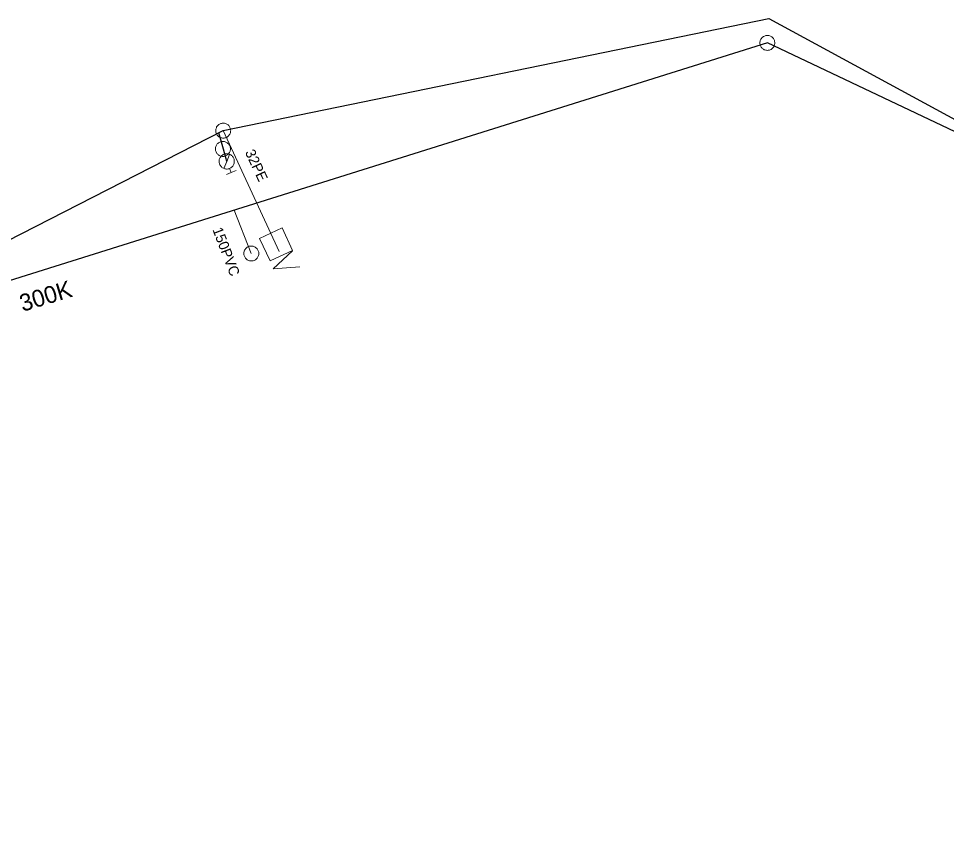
# Model space of a CAD drawing. Extents: x -741806 to -738704, y -1059275 to -1055387.
# Drawn here: x -740464.1 to -740409.8, y -1057633.9 to -1057586.1 of the extents above; entities that cross this region are included whole.
import ezdxf

# ---------------------------------------------------------------- set-up
doc = ezdxf.new("R2010")
doc.units = 0
doc.header["$LTSCALE"] = 0.4
for name, color, linetype, lineweight in [('2', 7, 'Continuous', 25), ('21', 7, 'Continuous', 13), ('3', 7, 'Continuous', 13), ('46', 7, 'Continuous', 13), ('50', 7, 'Continuous', 13), ('51', 7, 'Continuous', 13), ('52', 7, 'Continuous', 25), ('56', 7, 'Continuous', 13), ('60', 7, 'Continuous', 13)]:
    doc.layers.add(name, color=color, linetype=linetype, lineweight=lineweight)
for name, color, linetype in [('5', 7, 'Continuous'), ('54', 7, 'Continuous'), ('55', 7, 'Continuous')]:
    doc.layers.add(name, color=color, linetype=linetype)

msp = doc.modelspace()

# ---------------------------------------------------------------- linework, layer by layer
at = {"layer": '2'}
for p, q in [((-740420.289, -1057587.53), (-740504.877, -1057614.071)), ((-740388.249, -1057602.723), (-740420.289, -1057587.53))]:
    msp.add_line(p, q, dxfattribs=at)
at = {"layer": '21'}
msp.add_line((-740452.151, -1057592.668), (-740448.87, -1057599.747), dxfattribs=at)
at = {"layer": '3'}
msp.add_lwpolyline([(-740420.707, -1057587.66), (-740420.69, -1057587.702), (-740420.67, -1057587.743), (-740420.645, -1057587.782), (-740420.617, -1057587.818), (-740420.585, -1057587.85), (-740420.549, -1057587.88), (-740420.511, -1057587.905), (-740420.471, -1057587.927), (-740420.428, -1057587.943), (-740420.384, -1057587.955), (-740420.339, -1057587.963), (-740420.293, -1057587.966), (-740420.248, -1057587.964), (-740420.202, -1057587.958), (-740420.158, -1057587.946), (-740420.115, -1057587.93), (-740420.074, -1057587.909), (-740420.035, -1057587.886), (-740419.999, -1057587.856), (-740419.967, -1057587.824), (-740419.938, -1057587.789), (-740419.913, -1057587.752), (-740419.891, -1057587.71), (-740419.874, -1057587.668), (-740419.862, -1057587.624), (-740419.855, -1057587.578), (-740419.851, -1057587.533), (-740419.853, -1057587.487), (-740419.86, -1057587.442), (-740419.872, -1057587.397), (-740419.887, -1057587.355), (-740419.908, -1057587.314), (-740419.932, -1057587.275), (-740419.962, -1057587.239), (-740419.993, -1057587.207), (-740420.028, -1057587.177), (-740420.066, -1057587.152), (-740420.108, -1057587.131), (-740420.149, -1057587.114), (-740420.193, -1057587.102), (-740420.239, -1057587.094), (-740420.285, -1057587.091), (-740420.33, -1057587.092), (-740420.375, -1057587.099), (-740420.42, -1057587.111), (-740420.463, -1057587.127), (-740420.504, -1057587.147), (-740420.542, -1057587.172), (-740420.578, -1057587.201), (-740420.611, -1057587.233), (-740420.64, -1057587.268), (-740420.666, -1057587.306), (-740420.686, -1057587.347), (-740420.704, -1057587.389), (-740420.716, -1057587.434), (-740420.724, -1057587.479), (-740420.726, -1057587.524), (-740420.724, -1057587.57), (-740420.717, -1057587.615), (-740420.707, -1057587.659)], dxfattribs=at)
at = {"layer": '46'}
msp.add_lwpolyline([(-740450.665, -1057599.461), (-740450.706, -1057599.48), (-740450.746, -1057599.503), (-740450.783, -1057599.53), (-740450.816, -1057599.561), (-740450.847, -1057599.595), (-740450.874, -1057599.633), (-740450.896, -1057599.672), (-740450.915, -1057599.714), (-740450.928, -1057599.758), (-740450.938, -1057599.802), (-740450.942, -1057599.848), (-740450.943, -1057599.894), (-740450.937, -1057599.939), (-740450.928, -1057599.984), (-740450.913, -1057600.028), (-740450.894, -1057600.07), (-740450.871, -1057600.109), (-740450.844, -1057600.146), (-740450.813, -1057600.18), (-740450.778, -1057600.21), (-740450.741, -1057600.237), (-740450.702, -1057600.259), (-740450.66, -1057600.278), (-740450.616, -1057600.292), (-740450.571, -1057600.301), (-740450.526, -1057600.305), (-740450.48, -1057600.305), (-740450.434, -1057600.3), (-740450.39, -1057600.29), (-740450.346, -1057600.275), (-740450.305, -1057600.257), (-740450.265, -1057600.234), (-740450.228, -1057600.207), (-740450.194, -1057600.175), (-740450.164, -1057600.142), (-740450.137, -1057600.104), (-740450.115, -1057600.065), (-740450.096, -1057600.022), (-740450.083, -1057599.979), (-740450.073, -1057599.935), (-740450.069, -1057599.889), (-740450.068, -1057599.843), (-740450.073, -1057599.797), (-740450.083, -1057599.753), (-740450.098, -1057599.709), (-740450.117, -1057599.667), (-740450.14, -1057599.628), (-740450.167, -1057599.591), (-740450.198, -1057599.557), (-740450.233, -1057599.527), (-740450.27, -1057599.5), (-740450.309, -1057599.477), (-740450.351, -1057599.459), (-740450.395, -1057599.445), (-740450.44, -1057599.436), (-740450.486, -1057599.431), (-740450.531, -1057599.432), (-740450.577, -1057599.437), (-740450.621, -1057599.447), (-740450.664, -1057599.46)], dxfattribs=at)
at = {"layer": '50'}
for p, q in [((-740451.948, -1057594.472), (-740451.775, -1057594.059)), ((-740451.948, -1057594.472), (-740452.122, -1057594.88)), ((-740451.967, -1057595.234), (-740451.683, -1057595.118)), ((-740451.778, -1057594.886), (-740451.683, -1057595.118)), ((-740451.398, -1057595.002), (-740451.683, -1057595.118))]:
    msp.add_line(p, q, dxfattribs=at)
msp.add_lwpolyline([(-740452.361, -1057594.637), (-740452.339, -1057594.681), (-740452.317, -1057594.722), (-740452.288, -1057594.759), (-740452.256, -1057594.793), (-740452.223, -1057594.822), (-740452.183, -1057594.85), (-740452.143, -1057594.872), (-740452.099, -1057594.891), (-740452.055, -1057594.906), (-740452.009, -1057594.913), (-740451.963, -1057594.918), (-740451.916, -1057594.919), (-740451.869, -1057594.911), (-740451.824, -1057594.901), (-740451.78, -1057594.886), (-740451.739, -1057594.866), (-740451.699, -1057594.845), (-740451.661, -1057594.815), (-740451.627, -1057594.783), (-740451.595, -1057594.747), (-740451.569, -1057594.71), (-740451.546, -1057594.669), (-740451.528, -1057594.626), (-740451.514, -1057594.582), (-740451.504, -1057594.535), (-740451.5, -1057594.489), (-740451.501, -1057594.443), (-740451.506, -1057594.395), (-740451.518, -1057594.351), (-740451.53, -1057594.306), (-740451.551, -1057594.262), (-740451.576, -1057594.223), (-740451.602, -1057594.187), (-740451.635, -1057594.151), (-740451.67, -1057594.121), (-740451.708, -1057594.093), (-740451.749, -1057594.072), (-740451.792, -1057594.052), (-740451.838, -1057594.038), (-740451.882, -1057594.031), (-740451.931, -1057594.027), (-740451.976, -1057594.028), (-740452.022, -1057594.031), (-740452.07, -1057594.042), (-740452.114, -1057594.057), (-740452.155, -1057594.077), (-740452.195, -1057594.102), (-740452.233, -1057594.13), (-740452.267, -1057594.161), (-740452.298, -1057594.197), (-740452.324, -1057594.234), (-740452.348, -1057594.276), (-740452.366, -1057594.318), (-740452.38, -1057594.362), (-740452.387, -1057594.409), (-740452.394, -1057594.455), (-740452.393, -1057594.502), (-740452.385, -1057594.547), (-740452.375, -1057594.593)], close=True, dxfattribs=at)
at = {"layer": '51'}
for points in [[(-740451.967, -1057593.064), (-740451.927, -1057593.043), (-740451.889, -1057593.018), (-740451.854, -1057592.988), (-740451.822, -1057592.956), (-740451.794, -1057592.92), (-740451.769, -1057592.881), (-740451.749, -1057592.84), (-740451.733, -1057592.797), (-740451.723, -1057592.752), (-740451.716, -1057592.708), (-740451.714, -1057592.661), (-740451.717, -1057592.615), (-740451.724, -1057592.57), (-740451.737, -1057592.527), (-740451.754, -1057592.484), (-740451.776, -1057592.443), (-740451.801, -1057592.405), (-740451.83, -1057592.37), (-740451.864, -1057592.338), (-740451.9, -1057592.31), (-740451.939, -1057592.286), (-740451.979, -1057592.265), (-740452.023, -1057592.25), (-740452.067, -1057592.238), (-740452.112, -1057592.232), (-740452.159, -1057592.23), (-740452.203, -1057592.234), (-740452.249, -1057592.242), (-740452.293, -1057592.254), (-740452.336, -1057592.271), (-740452.376, -1057592.292), (-740452.413, -1057592.318), (-740452.449, -1057592.347), (-740452.481, -1057592.38), (-740452.509, -1057592.416), (-740452.534, -1057592.455), (-740452.553, -1057592.496), (-740452.57, -1057592.539), (-740452.58, -1057592.583), (-740452.587, -1057592.628), (-740452.589, -1057592.674), (-740452.586, -1057592.721), (-740452.578, -1057592.765), (-740452.566, -1057592.809), (-740452.548, -1057592.852), (-740452.527, -1057592.893), (-740452.501, -1057592.93), (-740452.473, -1057592.966), (-740452.439, -1057592.997), (-740452.403, -1057593.026), (-740452.364, -1057593.05), (-740452.324, -1057593.071), (-740452.28, -1057593.086), (-740452.236, -1057593.097), (-740452.19, -1057593.104), (-740452.144, -1057593.105), (-740452.099, -1057593.102), (-740452.054, -1057593.094), (-740452.01, -1057593.082), (-740451.968, -1057593.065)], [(-740452.262, -1057593.314), (-740452.306, -1057593.326), (-740452.348, -1057593.342), (-740452.389, -1057593.364), (-740452.427, -1057593.388), (-740452.463, -1057593.417), (-740452.495, -1057593.45), (-740452.523, -1057593.486), (-740452.549, -1057593.524), (-740452.569, -1057593.565), (-740452.585, -1057593.608), (-740452.597, -1057593.652), (-740452.604, -1057593.698), (-740452.607, -1057593.744), (-740452.604, -1057593.789), (-740452.596, -1057593.834), (-740452.584, -1057593.879), (-740452.568, -1057593.921), (-740452.547, -1057593.962), (-740452.521, -1057594), (-740452.492, -1057594.036), (-740452.459, -1057594.068), (-740452.424, -1057594.097), (-740452.385, -1057594.121), (-740452.345, -1057594.142), (-740452.301, -1057594.158), (-740452.257, -1057594.17), (-740452.212, -1057594.177), (-740452.166, -1057594.179), (-740452.12, -1057594.176), (-740452.075, -1057594.169), (-740452.032, -1057594.157), (-740451.989, -1057594.14), (-740451.948, -1057594.119), (-740451.91, -1057594.094), (-740451.874, -1057594.065), (-740451.842, -1057594.032), (-740451.814, -1057593.997), (-740451.788, -1057593.958), (-740451.768, -1057593.917), (-740451.752, -1057593.875), (-740451.74, -1057593.83), (-740451.733, -1057593.785), (-740451.731, -1057593.739), (-740451.733, -1057593.694), (-740451.741, -1057593.648), (-740451.753, -1057593.604), (-740451.77, -1057593.561), (-740451.79, -1057593.521), (-740451.816, -1057593.482), (-740451.845, -1057593.447), (-740451.878, -1057593.415), (-740451.913, -1057593.386), (-740451.952, -1057593.362), (-740451.992, -1057593.341), (-740452.036, -1057593.324), (-740452.08, -1057593.313), (-740452.125, -1057593.306), (-740452.171, -1057593.304), (-740452.217, -1057593.307), (-740452.261, -1057593.314)]]:
    msp.add_lwpolyline(points, dxfattribs=at)
at = {"layer": '52'}
for points in [[(-740503.249, -1057612.745), (-740480.638, -1057607.754), (-740465.682, -1057599.577), (-740452.151, -1057592.668), (-740420.197, -1057586.102), (-740388.602, -1057603.262), (-740371.388, -1057615.413), (-740359.399, -1057625.23), (-740352.519, -1057631.399), (-740349.517, -1057633.908)], [(-740451.947, -1057594.477), (-740451.98, -1057594.33), (-740452.14, -1057593.75), (-740452.403, -1057592.796)]]:
    msp.add_lwpolyline(points, dxfattribs=at)
at = {"layer": '56'}
msp.add_line((-740450.506, -1057599.869), (-740451.5, -1057597.323), dxfattribs=at)
at = {"layer": '60'}
msp.add_lwpolyline([(-740450.018, -1057598.984), (-740448.701, -1057598.373), (-740448.09, -1057599.691), (-740449.408, -1057600.301)], close=True, dxfattribs=at)
msp.add_lwpolyline([(-740448.103, -1057599.703), (-740449.221, -1057600.767), (-740447.668, -1057600.642)], dxfattribs=at)

# ---------------------------------------------------------------- texts
at = {"layer": '5'}
msp.add_text('300K', height=1, rotation=17, dxfattribs=at).set_placement((-740463.896, -1057603.292))
at = {"layer": '54'}
msp.add_text('32PE', height=0.6, rotation=295, dxfattribs=at).set_placement((-740450.888, -1057593.938))
at = {"layer": '55'}
msp.add_text('150PVC', height=0.6, rotation=291, dxfattribs=at).set_placement((-740452.788, -1057598.468))

doc.saveas('drawing.dxf')
